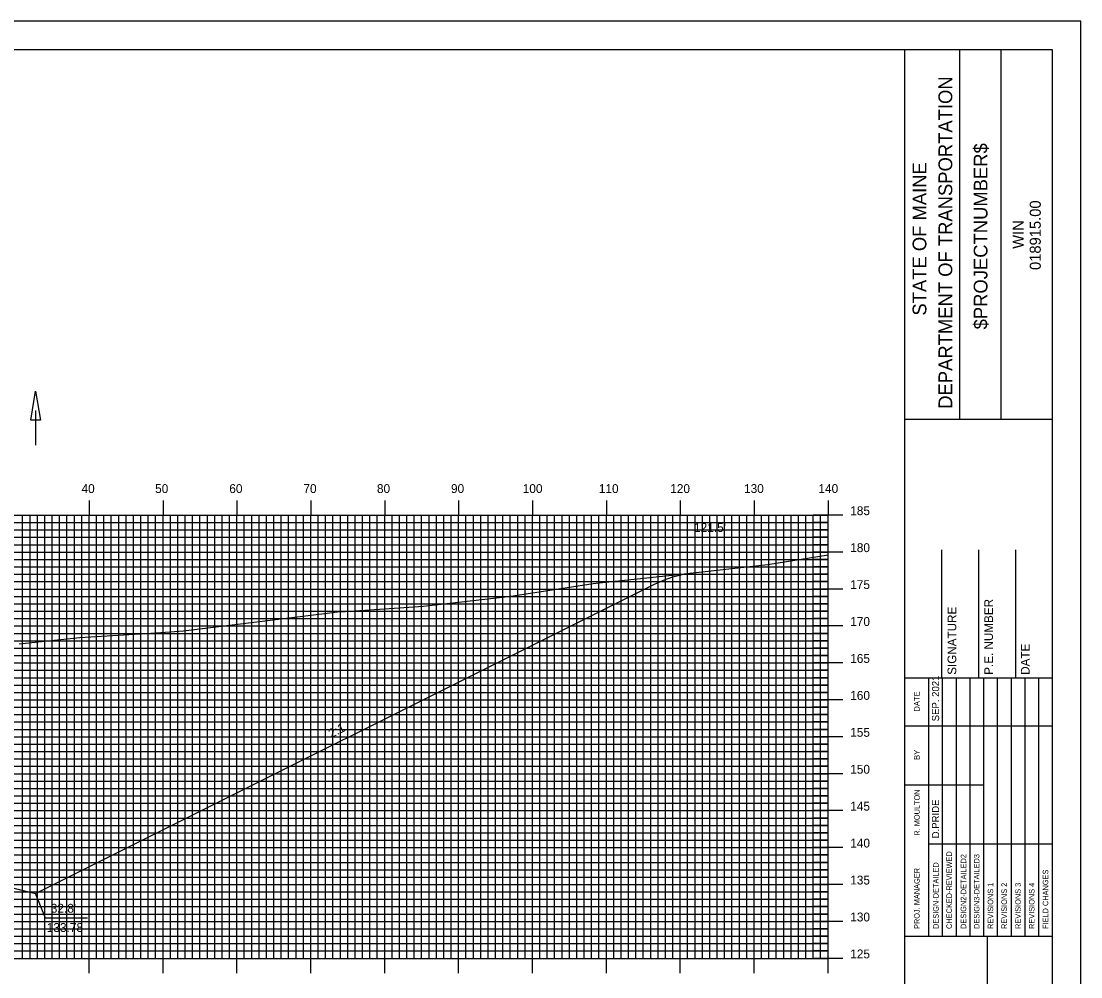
# Model space of a CAD drawing. Extents: x 1783828 to 1784171, y 442591 to 442811.
# Drawn here: x 1784024.3 to 1784167.7, y 442681.2 to 442810.5 of the extents above; entities that cross this region are included whole.
import ezdxf

# ---------------------------------------------------------------- set-up
doc = ezdxf.new("R2010")
doc.units = 0
for name, color, linetype in [('ANNOTATION', 7, 'Continuous'), ('BORDER', 7, 'Continuous'), ('D_Drainage_Ditch_Line', 7, 'Continuous'), ('D_Roadway_Centerline', 7, 'Continuous'), ('D_Roadway_SlopeLines', 7, 'Continuous'), ('D_Text_Standard', 7, 'Continuous'), ('H_V ANNOTATION', 7, 'Continuous'), ('MAJOR', 7, 'Continuous'), ('MINOR', 7, 'Continuous'), ('PLOT BOUNDARY', 7, 'Continuous'), ('S_Roadway_Centerline', 7, 'Continuous')]:
    doc.layers.add(name, color=color, linetype=linetype)

msp = doc.modelspace()

# ---------------------------------------------------------------- linework, layer by layer
at = {"layer": 'ANNOTATION'}
msp.add_lwpolyline([(1784033.28, 442689.13), (1784027.59, 442689.13), (1784026.24, 442692.45)], dxfattribs=at)
at = {"layer": 'BORDER'}
for p, q in [((1784143.89, 442596.67), (1784143.89, 442806.67)), ((1784151.34, 442756.66), (1784151.34, 442806.66)), ((1784156.93, 442756.66), (1784156.93, 442806.66)), ((1784143.89, 442756.65), (1784163.89, 442756.65)), ((1784143.89, 442756.65), (1784163.89, 442756.65)), ((1784148.89, 442721.67), (1784148.89, 442738.97)), ((1784148.89, 442721.67), (1784148.89, 442738.97)), ((1784153.89, 442721.67), (1784153.89, 442738.97)), ((1784153.89, 442721.67), (1784153.89, 442738.97)), ((1784158.89, 442721.67), (1784158.89, 442738.97)), ((1784158.89, 442721.67), (1784158.89, 442738.97)), ((1784143.89, 442721.67), (1784163.89, 442721.67)), ((1784143.89, 442721.67), (1784163.89, 442721.67)), ((1784143.89, 442686.67), (1784163.89, 442686.67)), ((1784143.89, 442686.67), (1784163.89, 442686.67)), ((1784155.07, 442616.67), (1784155.07, 442686.67)), ((1784155.07, 442616.67), (1784155.07, 442686.67))]:
    msp.add_line(p, q, dxfattribs=at)
msp.add_lwpolyline([(1783843.89, 442596.67), (1784163.89, 442596.67), (1784163.89, 442806.67), (1783843.89, 442806.67)], close=True, dxfattribs=at)
for points in [[(1784147.12, 442715.17), (1784147.12, 442721.67)], [(1784147.12, 442715.17), (1784147.12, 442721.67)], [(1784148.98, 442686.68), (1784148.98, 442721.67)], [(1784148.98, 442686.68), (1784148.98, 442721.67)], [(1784150.84, 442721.67), (1784150.84, 442686.68)], [(1784150.84, 442721.67), (1784150.84, 442686.68)], [(1784152.71, 442686.68), (1784152.71, 442721.67)], [(1784152.71, 442686.68), (1784152.71, 442721.67)], [(1784154.57, 442686.68), (1784154.57, 442721.67)], [(1784154.57, 442686.68), (1784154.57, 442721.67)], [(1784156.43, 442686.68), (1784156.43, 442721.67)], [(1784156.43, 442686.68), (1784156.43, 442721.67)], [(1784158.3, 442686.68), (1784158.3, 442721.67)], [(1784158.3, 442686.68), (1784158.3, 442721.67)], [(1784160.16, 442686.68), (1784160.16, 442721.67)], [(1784160.16, 442686.68), (1784160.16, 442721.67)], [(1784162.02, 442686.68), (1784162.02, 442721.67)], [(1784162.02, 442686.68), (1784162.02, 442721.67)], [(1784147.12, 442686.68), (1784147.12, 442720.26)], [(1784147.12, 442686.68), (1784147.12, 442720.26)], [(1784143.89, 442715.17), (1784163.89, 442715.17)], [(1784143.89, 442715.17), (1784163.89, 442715.17)], [(1784143.89, 442707.17), (1784147.12, 442707.17)], [(1784143.89, 442707.17), (1784147.12, 442707.17)], [(1784147.12, 442707.17), (1784154.57, 442707.17)], [(1784147.12, 442707.17), (1784154.57, 442707.17)], [(1784147.12, 442699.17), (1784163.89, 442699.17)], [(1784147.12, 442699.17), (1784163.89, 442699.17)]]:
    msp.add_lwpolyline(points, dxfattribs=at)
at = {"layer": 'D_Drainage_Ditch_Line'}
msp.add_line((1784026.24, 442757.86), (1784026.24, 442753.16), dxfattribs=at)
msp.add_lwpolyline([(1784026.89, 442756.55), (1784025.58, 442756.55), (1784026.24, 442760.48)], close=True, dxfattribs=at)
at = {"layer": 'D_Roadway_Centerline'}
msp.add_lwpolyline([(1783907.77, 442715.91), (1783909.02, 442715.91), (1783910.27, 442715.73), (1783911.52, 442715.37), (1783912.77, 442714.83), (1783959.31, 442691.56), (1783963.31, 442692.56), (1783973.49, 442695.11), (1783981.49, 442695.43), (1783993.49, 442695.69), (1784005.49, 442695.95), (1784013.49, 442695.63), (1784023.66, 442693.09), (1784026.24, 442692.45), (1784109.99, 442734.32), (1784111.24, 442734.89), (1784112.49, 442735.33), (1784113.74, 442735.65), (1784114.99, 442735.85)], dxfattribs=at)
at = {"layer": 'D_Roadway_SlopeLines'}
for points in [[(1784026.24, 442692.45), (1784109.99, 442734.32), (1784111.24, 442734.89), (1784112.49, 442735.33), (1784113.74, 442735.65), (1784114.99, 442735.85)], [(1784013.49, 442695.63), (1784026.24, 442692.45)]]:
    msp.add_lwpolyline(points, dxfattribs=at)
at = {"layer": 'MAJOR'}
for p, q in [((1784033.49, 442745.67), (1784033.49, 442743.67)), ((1784043.49, 442745.67), (1784043.49, 442743.67)), ((1784053.49, 442745.67), (1784053.49, 442743.67)), ((1784063.49, 442745.67), (1784063.49, 442743.67)), ((1784073.49, 442745.67), (1784073.49, 442743.67)), ((1784083.49, 442745.67), (1784083.49, 442743.67)), ((1784093.49, 442745.67), (1784093.49, 442743.67)), ((1784103.49, 442745.67), (1784103.49, 442743.67)), ((1784113.49, 442745.67), (1784113.49, 442743.67)), ((1784123.49, 442745.67), (1784123.49, 442743.67)), ((1784133.49, 442745.67), (1784133.49, 442743.67)), ((1783853.49, 442743.67), (1784133.49, 442743.67)), ((1783853.49, 442743.67), (1784133.49, 442743.67)), ((1784033.49, 442683.67), (1784033.49, 442743.67)), ((1784043.49, 442683.67), (1784043.49, 442743.67)), ((1784053.49, 442683.67), (1784053.49, 442743.67)), ((1784063.49, 442683.67), (1784063.49, 442743.67)), ((1784073.49, 442683.67), (1784073.49, 442743.67)), ((1784083.49, 442683.67), (1784083.49, 442743.67)), ((1784093.49, 442683.67), (1784093.49, 442743.67)), ((1784103.49, 442683.67), (1784103.49, 442743.67)), ((1784113.49, 442683.67), (1784113.49, 442743.67)), ((1784123.49, 442683.67), (1784123.49, 442743.67)), ((1784135.49, 442743.67), (1784131.48, 442743.67)), ((1784133.49, 442683.67), (1784133.49, 442743.67)), ((1784133.49, 442683.67), (1784133.49, 442743.67)), ((1783853.49, 442738.67), (1784133.49, 442738.67)), ((1784135.49, 442738.67), (1784131.48, 442738.67)), ((1783853.49, 442733.67), (1784133.49, 442733.67)), ((1784135.49, 442733.67), (1784131.48, 442733.67)), ((1783853.49, 442728.67), (1784133.49, 442728.67)), ((1784135.49, 442728.67), (1784131.48, 442728.67)), ((1783853.49, 442723.67), (1784133.49, 442723.67)), ((1784135.49, 442723.67), (1784131.48, 442723.67)), ((1783853.49, 442718.67), (1784133.49, 442718.67)), ((1784135.49, 442718.67), (1784131.48, 442718.67)), ((1783853.49, 442713.67), (1784133.49, 442713.67)), ((1784135.49, 442713.67), (1784131.48, 442713.67)), ((1783853.49, 442708.67), (1784133.49, 442708.67)), ((1784135.49, 442708.67), (1784131.48, 442708.67)), ((1783853.49, 442703.67), (1784133.49, 442703.67)), ((1784135.49, 442703.67), (1784131.48, 442703.67)), ((1783853.49, 442698.67), (1784133.49, 442698.67)), ((1784135.49, 442698.67), (1784131.48, 442698.67)), ((1783853.49, 442693.67), (1784133.49, 442693.67)), ((1784135.49, 442693.67), (1784131.48, 442693.67)), ((1783853.49, 442688.67), (1784133.49, 442688.67)), ((1784135.49, 442688.67), (1784131.48, 442688.67)), ((1783853.49, 442683.67), (1784133.49, 442683.67)), ((1783853.49, 442683.67), (1784133.49, 442683.67)), ((1784033.49, 442681.66), (1784033.49, 442683.67)), ((1784043.49, 442681.66), (1784043.49, 442683.67)), ((1784053.49, 442681.66), (1784053.49, 442683.67)), ((1784063.49, 442681.66), (1784063.49, 442683.67)), ((1784073.49, 442681.66), (1784073.49, 442683.67)), ((1784083.49, 442681.66), (1784083.49, 442683.67)), ((1784093.49, 442681.66), (1784093.49, 442683.67)), ((1784103.49, 442681.66), (1784103.49, 442683.67)), ((1784113.49, 442681.66), (1784113.49, 442683.67)), ((1784123.49, 442681.66), (1784123.49, 442683.67)), ((1784135.49, 442683.67), (1784131.48, 442683.67)), ((1784133.49, 442681.66), (1784133.49, 442683.67))]:
    msp.add_line(p, q, dxfattribs=at)
at = {"layer": 'MINOR'}
for p, q in [((1783853.49, 442742.67), (1784133.49, 442742.67)), ((1784024.49, 442683.67), (1784024.49, 442743.67)), ((1784025.49, 442683.67), (1784025.49, 442743.67)), ((1784026.49, 442683.67), (1784026.49, 442743.67)), ((1784027.49, 442683.67), (1784027.49, 442743.67)), ((1784028.49, 442683.67), (1784028.49, 442743.67)), ((1784029.49, 442683.67), (1784029.49, 442743.67)), ((1784030.49, 442683.67), (1784030.49, 442743.67)), ((1784031.49, 442683.67), (1784031.49, 442743.67)), ((1784032.49, 442683.67), (1784032.49, 442743.67)), ((1784034.49, 442683.67), (1784034.49, 442743.67)), ((1784035.49, 442683.67), (1784035.49, 442743.67)), ((1784036.49, 442683.67), (1784036.49, 442743.67)), ((1784037.49, 442683.67), (1784037.49, 442743.67)), ((1784038.49, 442683.67), (1784038.49, 442743.67)), ((1784039.49, 442683.67), (1784039.49, 442743.67)), ((1784040.49, 442683.67), (1784040.49, 442743.67)), ((1784041.49, 442683.67), (1784041.49, 442743.67)), ((1784042.49, 442683.67), (1784042.49, 442743.67)), ((1784044.49, 442683.67), (1784044.49, 442743.67)), ((1784045.49, 442683.67), (1784045.49, 442743.67)), ((1784046.49, 442683.67), (1784046.49, 442743.67)), ((1784047.49, 442683.67), (1784047.49, 442743.67)), ((1784048.49, 442683.67), (1784048.49, 442743.67)), ((1784049.49, 442683.67), (1784049.49, 442743.67)), ((1784050.49, 442683.67), (1784050.49, 442743.67)), ((1784051.49, 442683.67), (1784051.49, 442743.67)), ((1784052.49, 442683.67), (1784052.49, 442743.67)), ((1784054.49, 442683.67), (1784054.49, 442743.67)), ((1784055.49, 442683.67), (1784055.49, 442743.67)), ((1784056.49, 442683.67), (1784056.49, 442743.67)), ((1784057.49, 442683.67), (1784057.49, 442743.67)), ((1784058.49, 442683.67), (1784058.49, 442743.67)), ((1784059.49, 442683.67), (1784059.49, 442743.67)), ((1784060.49, 442683.67), (1784060.49, 442743.67)), ((1784061.49, 442683.67), (1784061.49, 442743.67)), ((1784062.49, 442683.67), (1784062.49, 442743.67)), ((1784064.49, 442683.67), (1784064.49, 442743.67)), ((1784065.49, 442683.67), (1784065.49, 442743.67)), ((1784066.49, 442683.67), (1784066.49, 442743.67)), ((1784067.49, 442683.67), (1784067.49, 442743.67)), ((1784068.49, 442683.67), (1784068.49, 442743.67)), ((1784069.49, 442683.67), (1784069.49, 442743.67)), ((1784070.49, 442683.67), (1784070.49, 442743.67)), ((1784071.49, 442683.67), (1784071.49, 442743.67)), ((1784072.49, 442683.67), (1784072.49, 442743.67)), ((1784074.49, 442683.67), (1784074.49, 442743.67)), ((1784075.49, 442683.67), (1784075.49, 442743.67)), ((1784076.49, 442683.67), (1784076.49, 442743.67)), ((1784077.49, 442683.67), (1784077.49, 442743.67)), ((1784078.49, 442683.67), (1784078.49, 442743.67)), ((1784079.49, 442683.67), (1784079.49, 442743.67)), ((1784080.49, 442683.67), (1784080.49, 442743.67)), ((1784081.49, 442683.67), (1784081.49, 442743.67)), ((1784082.49, 442683.67), (1784082.49, 442743.67)), ((1784084.49, 442683.67), (1784084.49, 442743.67)), ((1784085.49, 442683.67), (1784085.49, 442743.67)), ((1784086.49, 442683.67), (1784086.49, 442743.67)), ((1784087.49, 442683.67), (1784087.49, 442743.67)), ((1784088.49, 442683.67), (1784088.49, 442743.67)), ((1784089.49, 442683.67), (1784089.49, 442743.67)), ((1784090.49, 442683.67), (1784090.49, 442743.67)), ((1784091.49, 442683.67), (1784091.49, 442743.67)), ((1784092.49, 442683.67), (1784092.49, 442743.67)), ((1784094.49, 442683.67), (1784094.49, 442743.67)), ((1784095.49, 442683.67), (1784095.49, 442743.67)), ((1784096.49, 442683.67), (1784096.49, 442743.67)), ((1784097.49, 442683.67), (1784097.49, 442743.67)), ((1784098.49, 442683.67), (1784098.49, 442743.67)), ((1784099.49, 442683.67), (1784099.49, 442743.67)), ((1784100.49, 442683.67), (1784100.49, 442743.67)), ((1784101.49, 442683.67), (1784101.49, 442743.67)), ((1784102.49, 442683.67), (1784102.49, 442743.67)), ((1784104.49, 442683.67), (1784104.49, 442743.67)), ((1784105.49, 442683.67), (1784105.49, 442743.67)), ((1784106.49, 442683.67), (1784106.49, 442743.67)), ((1784107.49, 442683.67), (1784107.49, 442743.67)), ((1784108.49, 442683.67), (1784108.49, 442743.67)), ((1784109.49, 442683.67), (1784109.49, 442743.67)), ((1784110.49, 442683.67), (1784110.49, 442743.67)), ((1784111.49, 442683.67), (1784111.49, 442743.67)), ((1784112.49, 442683.67), (1784112.49, 442743.67)), ((1784114.49, 442683.67), (1784114.49, 442743.67)), ((1784115.49, 442683.67), (1784115.49, 442743.67)), ((1784116.49, 442683.67), (1784116.49, 442743.67)), ((1784117.49, 442683.67), (1784117.49, 442743.67)), ((1784118.49, 442683.67), (1784118.49, 442743.67)), ((1784119.49, 442683.67), (1784119.49, 442743.67)), ((1784120.49, 442683.67), (1784120.49, 442743.67)), ((1784121.49, 442683.67), (1784121.49, 442743.67)), ((1784122.49, 442683.67), (1784122.49, 442743.67)), ((1784124.49, 442683.67), (1784124.49, 442743.67)), ((1784125.49, 442683.67), (1784125.49, 442743.67)), ((1784126.49, 442683.67), (1784126.49, 442743.67)), ((1784127.49, 442683.67), (1784127.49, 442743.67)), ((1784128.49, 442683.67), (1784128.49, 442743.67)), ((1784129.49, 442683.67), (1784129.49, 442743.67)), ((1784130.49, 442683.67), (1784130.49, 442743.67)), ((1784133.49, 442742.67), (1784131.48, 442742.67)), ((1784131.49, 442683.67), (1784131.49, 442743.67)), ((1784132.49, 442683.67), (1784132.49, 442743.67)), ((1783853.49, 442741.67), (1784133.49, 442741.67)), ((1784133.49, 442741.67), (1784131.48, 442741.67)), ((1783853.49, 442740.67), (1784133.49, 442740.67)), ((1784133.49, 442740.67), (1784131.48, 442740.67)), ((1783853.49, 442739.67), (1784133.49, 442739.67)), ((1784133.49, 442739.67), (1784131.48, 442739.67)), ((1783853.49, 442737.67), (1784133.49, 442737.67)), ((1784133.49, 442737.67), (1784131.48, 442737.67)), ((1783853.49, 442736.67), (1784133.49, 442736.67)), ((1783853.49, 442735.67), (1784133.49, 442735.67)), ((1784133.49, 442736.67), (1784131.48, 442736.67)), ((1784133.49, 442735.67), (1784131.48, 442735.67)), ((1783853.49, 442734.67), (1784133.49, 442734.67)), ((1784133.49, 442734.67), (1784131.48, 442734.67)), ((1783853.49, 442732.67), (1784133.49, 442732.67)), ((1784133.49, 442732.67), (1784131.48, 442732.67)), ((1783853.49, 442731.67), (1784133.49, 442731.67)), ((1784133.49, 442731.67), (1784131.48, 442731.67)), ((1783853.49, 442730.67), (1784133.49, 442730.67)), ((1784133.49, 442730.67), (1784131.48, 442730.67)), ((1783853.49, 442729.67), (1784133.49, 442729.67)), ((1784133.49, 442729.67), (1784131.48, 442729.67)), ((1783853.49, 442727.67), (1784133.49, 442727.67)), ((1784133.49, 442727.67), (1784131.48, 442727.67)), ((1783853.49, 442726.67), (1784133.49, 442726.67)), ((1783853.49, 442725.67), (1784133.49, 442725.67)), ((1784133.49, 442726.67), (1784131.48, 442726.67)), ((1784133.49, 442725.67), (1784131.48, 442725.67)), ((1783853.49, 442724.67), (1784133.49, 442724.67)), ((1784133.49, 442724.67), (1784131.48, 442724.67)), ((1783853.49, 442722.67), (1784133.49, 442722.67)), ((1784133.49, 442722.67), (1784131.48, 442722.67)), ((1783853.49, 442721.67), (1784133.49, 442721.67)), ((1784133.49, 442721.67), (1784131.48, 442721.67)), ((1783853.49, 442720.67), (1784133.49, 442720.67)), ((1783853.49, 442719.67), (1784133.49, 442719.67)), ((1784133.49, 442720.67), (1784131.48, 442720.67)), ((1784133.49, 442719.67), (1784131.48, 442719.67)), ((1783853.49, 442717.67), (1784133.49, 442717.67)), ((1784133.49, 442717.67), (1784131.48, 442717.67)), ((1783853.49, 442716.67), (1784133.49, 442716.67)), ((1783853.49, 442715.67), (1784133.49, 442715.67)), ((1784133.49, 442716.67), (1784131.48, 442716.67)), ((1784133.49, 442715.67), (1784131.48, 442715.67)), ((1783853.49, 442714.67), (1784133.49, 442714.67)), ((1784133.49, 442714.67), (1784131.48, 442714.67)), ((1783853.49, 442712.67), (1784133.49, 442712.67)), ((1784133.49, 442712.67), (1784131.48, 442712.67)), ((1783853.49, 442711.67), (1784133.49, 442711.67)), ((1784133.49, 442711.67), (1784131.48, 442711.67)), ((1783853.49, 442710.67), (1784133.49, 442710.67)), ((1783853.49, 442709.67), (1784133.49, 442709.67)), ((1784133.49, 442710.67), (1784131.48, 442710.67)), ((1784133.49, 442709.67), (1784131.48, 442709.67)), ((1783853.49, 442707.67), (1784133.49, 442707.67)), ((1784133.49, 442707.67), (1784131.48, 442707.67)), ((1783853.49, 442706.67), (1784133.49, 442706.67)), ((1783853.49, 442705.67), (1784133.49, 442705.67)), ((1784133.49, 442706.67), (1784131.48, 442706.67)), ((1784133.49, 442705.67), (1784131.48, 442705.67)), ((1783853.49, 442704.67), (1784133.49, 442704.67)), ((1784133.49, 442704.67), (1784131.48, 442704.67)), ((1783853.49, 442702.67), (1784133.49, 442702.67)), ((1784133.49, 442702.67), (1784131.48, 442702.67)), ((1783853.49, 442701.67), (1784133.49, 442701.67)), ((1784133.49, 442701.67), (1784131.48, 442701.67)), ((1783853.49, 442700.67), (1784133.49, 442700.67)), ((1783853.49, 442699.67), (1784133.49, 442699.67)), ((1784133.49, 442700.67), (1784131.48, 442700.67)), ((1784133.49, 442699.67), (1784131.48, 442699.67)), ((1783853.49, 442697.67), (1784133.49, 442697.67)), ((1784133.49, 442697.67), (1784131.48, 442697.67)), ((1783853.49, 442696.67), (1784133.49, 442696.67)), ((1783853.49, 442695.67), (1784133.49, 442695.67)), ((1784133.49, 442696.67), (1784131.48, 442696.67)), ((1784133.49, 442695.67), (1784131.48, 442695.67)), ((1783853.49, 442694.67), (1784133.49, 442694.67)), ((1784133.49, 442694.67), (1784131.48, 442694.67)), ((1783853.49, 442692.67), (1784133.49, 442692.67)), ((1784133.49, 442692.67), (1784131.48, 442692.67)), ((1783853.49, 442691.67), (1784133.49, 442691.67)), ((1784133.49, 442691.67), (1784131.48, 442691.67)), ((1783853.49, 442690.67), (1784133.49, 442690.67)), ((1783853.49, 442689.67), (1784133.49, 442689.67)), ((1784133.49, 442690.67), (1784131.48, 442690.67)), ((1784133.49, 442689.67), (1784131.48, 442689.67)), ((1783853.49, 442687.67), (1784133.49, 442687.67)), ((1784133.49, 442687.67), (1784131.48, 442687.67)), ((1783853.49, 442686.67), (1784133.49, 442686.67)), ((1783853.49, 442685.67), (1784133.49, 442685.67)), ((1784133.49, 442686.67), (1784131.48, 442686.67)), ((1784133.49, 442685.67), (1784131.48, 442685.67)), ((1783853.49, 442684.67), (1784133.49, 442684.67)), ((1784133.49, 442684.67), (1784131.48, 442684.67))]:
    msp.add_line(p, q, dxfattribs=at)
at = {"layer": 'PLOT BOUNDARY'}
msp.add_lwpolyline([(1783827.7, 442590.55), (1784167.7, 442590.55), (1784167.7, 442810.55), (1783827.7, 442810.55)], close=True, dxfattribs=at)
at = {"layer": 'S_Roadway_Centerline'}
msp.add_lwpolyline([(1784024.01, 442726.23), (1784032.25, 442727.12), (1784042.56, 442727.75), (1784046.28, 442727.99), (1784066.07, 442730.43), (1784067.09, 442730.59), (1784068.12, 442730.61), (1784078.76, 442731.34), (1784090.2, 442732.68), (1784090.89, 442732.77), (1784101.7, 442734.41), (1784113.21, 442735.65), (1784125.33, 442737.01), (1784133.49, 442738.31)], dxfattribs=at)

# ---------------------------------------------------------------- texts
at = {"layer": 'ANNOTATION'}
msp.add_text('2:1', height=1.2, rotation=26.5651, dxfattribs=at).set_placement((1784066.26, 442713.49))
for s, p in [("32.8'", (1784028.3, 442689.85)), ('133.78', (1784027.76, 442687.25))]:
    msp.add_text(s, height=1.2, dxfattribs=at).set_placement(p)
at = {"layer": 'BORDER'}
for s, height, p in [('DEPARTMENT OF TRANSPORTATION', 1.8635, (1784150.3, 442758.08)), ('$PROJECTNUMBER$', 1.8635, (1784155.07, 442768.82)), ('STATE OF MAINE', 1.8635, (1784146.8, 442770.69)), ('018915.00', 1.491, (1784162.28, 442776.86)), ('WIN', 1.491, (1784159.96, 442779.73)), ('SIGNATURE', 1.181, (1784150.85, 442722.06)), ('SIGNATURE', 1.181, (1784150.85, 442722.06)), ('P.E. NUMBER', 1.1811, (1784155.81, 442722.06)), ('P.E. NUMBER', 1.1811, (1784155.81, 442722.06)), ('DATE', 1.181, (1784160.77, 442722.06)), ('DATE', 1.181, (1784160.77, 442722.06)), ('SEP. 2021', 0.969, (1784148.53, 442715.76)), ('DATE', 0.743, (1784145.89, 442717.08)), ('DATE', 0.743, (1784145.89, 442717.08)), ('BY', 0.743, (1784145.89, 442710.54)), ('BY', 0.743, (1784145.89, 442710.54)), ('R. MOULTON', 0.745, (1784145.9, 442700.28)), ('D.PRIDE', 0.969, (1784148.53, 442699.92)), ('CHECKED-REVIEWED', 0.7455, (1784150.25, 442687.65)), ('CHECKED-REVIEWED', 0.7455, (1784150.25, 442687.65)), ('DESIGN2-DETAILED2', 0.7455, (1784152.19, 442687.65)), ('DESIGN2-DETAILED2', 0.7455, (1784152.19, 442687.65)), ('DESIGN3-DETAILED3', 0.7455, (1784153.98, 442687.65)), ('DESIGN3-DETAILED3', 0.7455, (1784153.98, 442687.65)), ('PROJ. MANAGER', 0.7455, (1784145.89, 442687.65)), ('PROJ. MANAGER', 0.7455, (1784145.89, 442687.65)), ('DESIGN-DETAILED', 0.7455, (1784148.46, 442687.65)), ('DESIGN-DETAILED', 0.7455, (1784148.46, 442687.65)), ('FIELD CHANGES', 0.7455, (1784163.29, 442687.65)), ('FIELD CHANGES', 0.7455, (1784163.29, 442687.65)), ('REVISIONS 1', 0.7455, (1784155.84, 442687.65)), ('REVISIONS 1', 0.7455, (1784155.84, 442687.65)), ('REVISIONS 2', 0.7455, (1784157.7, 442687.65)), ('REVISIONS 2', 0.7455, (1784157.7, 442687.65)), ('REVISIONS 3', 0.7455, (1784159.57, 442687.65)), ('REVISIONS 3', 0.7455, (1784159.57, 442687.65)), ('REVISIONS 4', 0.7455, (1784161.43, 442687.65)), ('REVISIONS 4', 0.7455, (1784161.43, 442687.65))]:
    msp.add_text(s, height=height, rotation=90, dxfattribs=at).set_placement(p)
at = {"layer": 'D_Text_Standard'}
msp.add_text("121.5'", height=1.2, dxfattribs=at).set_placement((1784115.36, 442741.4))
at = {"layer": 'H_V ANNOTATION'}
for s, p in [('40', (1784032.46, 442746.67)), ('50', (1784042.42, 442746.67)), ('60', (1784052.46, 442746.67)), ('70', (1784062.49, 442746.67)), ('80', (1784072.44, 442746.67)), ('90', (1784082.46, 442746.67)), ('100', (1784092.17, 442746.67)), ('110', (1784102.47, 442746.67)), ('120', (1784112.13, 442746.67)), ('130', (1784122.12, 442746.67)), ('140', (1784132.19, 442746.67)), ('185', (1784136.49, 442743.67)), ('180', (1784136.49, 442738.67)), ('175', (1784136.49, 442733.67)), ('170', (1784136.49, 442728.67)), ('165', (1784136.49, 442723.67)), ('160', (1784136.49, 442718.67)), ('155', (1784136.49, 442713.67)), ('150', (1784136.49, 442708.67)), ('145', (1784136.49, 442703.67)), ('140', (1784136.49, 442698.67)), ('135', (1784136.49, 442693.67)), ('130', (1784136.49, 442688.67)), ('125', (1784136.49, 442683.67))]:
    msp.add_text(s, height=1.2, dxfattribs=at).set_placement(p)

doc.saveas('drawing.dxf')
